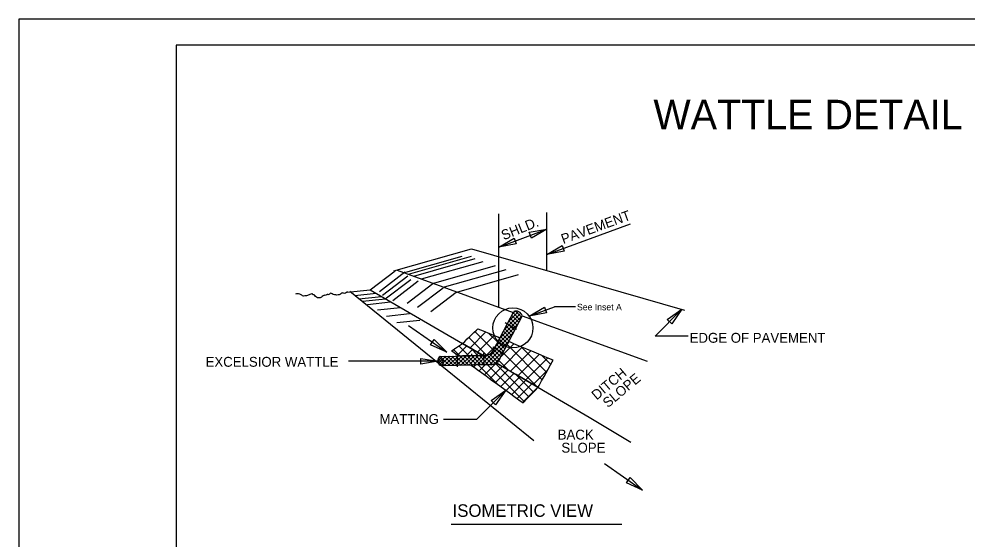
# Model space of a CAD drawing. Extents: x 8096 to 9796, y 9620 to 10720.
# Drawn here: x 8096 to 9099, y 10170 to 10720 of the extents above; entities that cross this region are included whole.
import ezdxf

# ---------------------------------------------------------------- set-up
doc = ezdxf.new("R2010")
doc.units = 0
for name, color, linetype in [('Blank Plan Sheet Both CELL', 7, 'Continuous'), ('Default', 7, 'Continuous'), ('Old_Level_1', 7, 'Continuous'), ('Old_Level_2', 7, 'Continuous'), ('Sheet Plot Border Outside CELL', 7, 'Continuous')]:
    doc.layers.add(name, color=color, linetype=linetype)

msp = doc.modelspace()

# ---------------------------------------------------------------- linework, layer by layer
at = {"layer": 'Blank Plan Sheet Both CELL'}
msp.add_line((8262, 10692.3), (8262, 10692.3), dxfattribs=at)
msp.add_lwpolyline([(9762, 10692.3), (8262, 10692.3), (8262, 9642.3), (9762, 9642.3)], close=True, dxfattribs=at)
at = {"layer": 'Default'}
for p, q in [((8597.6, 10369.4), (8619.1, 10410.3)), ((8597.6, 10369.4), (8619.1, 10410.3)), ((8597.6, 10369.4), (8619.1, 10410.3)), ((8628.1, 10406), (8603.7, 10359.6)), ((8628.1, 10406), (8603.7, 10359.6)), ((8628.1, 10406), (8603.7, 10359.6)), ((8604.2, 10382.1), (8628, 10405.8)), ((8608.9, 10390.9), (8626.6, 10408.6)), ((8613.6, 10399.9), (8624.1, 10410.4)), ((8616.9, 10406.1), (8624.3, 10398.7)), ((8618.3, 10408.8), (8620.1, 10410.6)), ((8618.3, 10408.9), (8625.7, 10401.5)), ((8620.8, 10410.7), (8627.2, 10404.3)), ((8599.5, 10373), (8623.3, 10396.9)), ((8611, 10395), (8618.4, 10387.6)), ((8612.5, 10397.8), (8619.9, 10390.4)), ((8614, 10400.6), (8621.4, 10393.2)), ((8615.4, 10403.4), (8622.8, 10395.9)), ((8572.8, 10372.2), (8589.4, 10388.8)), ((8578, 10389.3), (8597.7, 10369.7)), ((8580.8, 10367.5), (8598.4, 10385.1)), ((8584.7, 10354), (8618.6, 10387.9)), ((8592.5, 10387.6), (8602.1, 10378)), ((8605.2, 10383.9), (8612.6, 10376.5)), ((8606.6, 10386.7), (8614, 10379.3)), ((8608.1, 10389.5), (8615.5, 10382)), ((8609.6, 10392.2), (8617, 10384.8)), ((8559.7, 10364.3), (8569.5, 10374.1)), ((8561.1, 10374.1), (8571.6, 10363.7)), ((8565.1, 10376.8), (8565.5, 10376.4)), ((8571.6, 10383), (8590.4, 10364.3)), ((8589, 10354.1), (8613.9, 10379)), ((8590.3, 10364.2), (8599.9, 10373.8)), ((8600.8, 10375.6), (8608.2, 10368.1)), ((8602.3, 10378.3), (8609.7, 10370.9)), ((8603.7, 10381.1), (8611.1, 10373.7)), ((8605.3, 10362.6), (8619.1, 10376.4)), ((8612, 10375.4), (8649.2, 10338.1)), ((8541.4, 10363), (8589, 10364.1)), ((8541.4, 10363), (8589, 10364.1)), ((8541.4, 10363), (8589, 10364.1)), ((8545.6, 10353.1), (8555.8, 10363.3)), ((8549.9, 10353.2), (8560.1, 10363.4)), ((8553.7, 10363.3), (8563.5, 10353.5)), ((8553.9, 10368.4), (8556.8, 10371.3)), ((8554.2, 10353.3), (8564.5, 10363.5)), ((8555.2, 10370.2), (8561.9, 10363.5)), ((8557.8, 10363.4), (8567.6, 10353.6)), ((8558.6, 10353.4), (8568.8, 10363.6)), ((8562, 10363.5), (8571.7, 10353.7)), ((8562.9, 10353.5), (8573.2, 10363.7)), ((8566.1, 10363.6), (8575.9, 10353.8)), ((8567.3, 10353.6), (8577.5, 10363.8)), ((8568.9, 10363.6), (8575.8, 10370.5)), ((8570.3, 10363.7), (8580, 10353.9)), ((8571.6, 10353.7), (8581.9, 10363.9)), ((8573.2, 10371.9), (8581.2, 10363.9)), ((8574.4, 10363.8), (8584.2, 10354)), ((8576, 10353.8), (8586.2, 10364)), ((8578.5, 10363.9), (8588.3, 10354.1)), ((8579.1, 10363.9), (8582, 10366.8)), ((8580.3, 10353.9), (8590.8, 10364.3)), ((8582.7, 10364), (8592.5, 10354.2)), ((8586.8, 10364.1), (8596.5, 10354.4)), ((8590.8, 10364.3), (8599.6, 10355.5)), ((8593.4, 10354.2), (8609.2, 10370)), ((8593.8, 10365.5), (8602, 10357.3)), ((8596.2, 10367.4), (8603.8, 10359.8)), ((8597.9, 10370), (8605.3, 10362.6)), ((8599.3, 10372.8), (8606.7, 10365.4)), ((8607.5, 10352), (8628.1, 10372.7)), ((8607.6, 10367), (8643.6, 10331)), ((8615.5, 10347.4), (8637.1, 10368.9)), ((8623.6, 10342.7), (8646, 10365.1)), ((8626.9, 10373.1), (8653.8, 10346.3)), ((8648.8, 10364), (8658.3, 10354.5)), ((8538.6, 10357.9), (8542.6, 10361.9)), ((8538.6, 10358.2), (8543.3, 10353.5)), ((8539.1, 10360.5), (8544.2, 10355.5)), ((8539.2, 10355.7), (8543.7, 10360.2)), ((8540.3, 10362.2), (8544.4, 10358.1)), ((8540.5, 10354.2), (8544.4, 10358)), ((8542.1, 10362.4), (8542.8, 10363)), ((8542.3, 10353.2), (8544, 10354.8)), ((8595.1, 10354.2), (8543, 10353)), ((8595.1, 10354.2), (8543, 10353)), ((8595.1, 10354.2), (8543, 10353)), ((8543.4, 10360.8), (8551, 10353.2)), ((8543.9, 10359.9), (8547.1, 10363.1)), ((8544.2, 10355.7), (8546.9, 10353.1)), ((8544.3, 10356.1), (8551.5, 10363.2)), ((8545.4, 10363.1), (8555.2, 10353.3)), ((8549.5, 10363.2), (8559.3, 10353.4)), ((8576.7, 10351.8), (8578.8, 10353.9)), ((8581.6, 10353.9), (8602.2, 10333.3)), ((8582.5, 10347.7), (8588.9, 10354.1)), ((8588.2, 10343.5), (8600.7, 10356)), ((8591.3, 10354.2), (8630.2, 10315.2)), ((8598.2, 10354.9), (8604.5, 10361.1)), ((8599.8, 10355.6), (8635.1, 10320.2)), ((8603.2, 10358.7), (8613.2, 10348.7)), ((8631.6, 10338), (8655, 10361.4)), ((8593.9, 10339.3), (8606.9, 10352.3)), ((8599.7, 10335.2), (8613.2, 10348.7)), ((8605.4, 10331), (8619.5, 10345.1)), ((8621.2, 10344), (8640, 10325.3)), ((8639.6, 10333.3), (8655.2, 10348.8)), ((8611.2, 10326.9), (8625.7, 10341.4)), ((8616.9, 10322.7), (8632, 10337.8)), ((8622.6, 10318.5), (8638.2, 10334.1)), ((8628.4, 10314.4), (8644.5, 10330.5))]:
    msp.add_line(p, q, dxfattribs=at)
for points in [[(8565, 10376.7), (8567.2, 10378.8), (8569.9, 10381.4), (8572.6, 10384), (8576.8, 10388.1), (8579.5, 10390.8), (8581.1, 10392.3), (8586.6, 10390), (8593.6, 10387.1), (8595.2, 10386.5), (8598.3, 10385.2), (8602.2, 10383.5), (8604.5, 10382.5), (8603.5, 10380.6), (8602.6, 10378.9), (8601.4, 10376.7), (8599.8, 10373.7), (8597.9, 10370), (8597.2, 10368.8), (8596.6, 10368), (8595.9, 10367.2), (8595.1, 10366.4), (8594.6, 10366), (8593.7, 10365.5), (8593.1, 10365.1), (8592.4, 10364.8), (8591.8, 10364.6), (8591.3, 10364.4), (8590.7, 10364.3), (8589.9, 10364.2), (8589.2, 10364.1), (8588, 10364.1), (8587.5, 10364.1), (8586.8, 10364.1)], [(8565, 10376.7), (8575.4, 10370.7), (8583.9, 10365.8), (8586.8, 10364.1), (8582.5, 10363.9), (8572.6, 10363.7), (8564.8, 10363.5), (8560.8, 10363.4), (8553.2, 10368.9)], [(8600.6, 10356), (8604.6, 10353.7), (8607.8, 10351.8), (8613.2, 10348.7), (8618.4, 10345.7), (8623.3, 10342.8), (8627.9, 10340.2), (8632, 10337.8), (8637.7, 10334.5), (8641.8, 10332.1), (8644.9, 10330.3), (8645.9, 10332.2), (8648.6, 10337), (8651.2, 10341.8), (8653.4, 10345.6), (8655.5, 10349.4), (8658.1, 10354.2), (8659.7, 10357.1), (8660.8, 10359), (8654.5, 10361.6), (8648.1, 10364.3), (8640.6, 10367.4), (8633, 10370.6), (8624.1, 10374.3), (8619.3, 10376.3), (8616.3, 10377.6), (8613.8, 10378.7), (8612.6, 10376.6), (8612, 10375.4), (8610.7, 10372.9), (8609.2, 10370.1), (8607.4, 10366.6), (8605.5, 10363), (8604.3, 10360.7), (8603.1, 10358.7), (8602.5, 10357.8), (8601.8, 10357), (8601, 10356.4)], [(8600.6, 10356), (8600.1, 10355.7), (8599.5, 10355.4), (8598.9, 10355.1), (8598.1, 10354.8), (8597.5, 10354.6), (8596.5, 10354.4), (8595.9, 10354.3), (8594.5, 10354.3), (8592.9, 10354.2), (8589.7, 10354.1), (8587.4, 10354.1), (8584.5, 10354), (8581.4, 10353.9), (8577.2, 10353.8), (8574.1, 10353.7), (8575.5, 10352.8), (8578.2, 10350.8), (8580.2, 10349.3), (8585, 10345.8), (8589.8, 10342.4), (8595.3, 10338.3), (8601.8, 10333.7), (8608.2, 10329), (8614.6, 10324.3), (8620.7, 10319.9), (8624.5, 10317.2), (8629, 10313.9), (8633.7, 10318.8), (8638, 10323.2), (8641.7, 10327), (8644.9, 10330.3), (8637.2, 10334.8), (8621.7, 10343.7), (8614, 10348.2), (8606.3, 10352.7)]]:
    msp.add_lwpolyline(points, close=True, dxfattribs=at)
msp.add_circle((8618.2, 10393.1), 21.2, dxfattribs=at)
for centre, radius, start, end in [((8621.6, 10404.1), 6.73, 16.3003, 112.3538), ((8621.6, 10404.1), 6.73, 16.3003, 112.3538), ((8621.6, 10404.1), 6.73, 16.3003, 112.3538), ((8588.7, 10374.1), 10, 271.3629, 332.2541), ((8588.7, 10374.1), 10, 271.3629, 332.2541), ((8588.7, 10374.1), 10, 271.3629, 332.2541), ((8543.9, 10358.3), 5.34, 118.1483, 259.9808), ((8537.6, 10357.2), 6.89, 321.9603, 56.1688), ((8537.6, 10357.2), 6.89, 321.9603, 56.1688), ((8537.6, 10357.2), 6.89, 321.9603, 56.1688), ((8537.6, 10357.2), 6.89, 321.9603, 56.1688), ((8537.6, 10357.2), 6.89, 321.9603, 56.1688), ((8594.8, 10364.2), 10, 271.3629, 332.2541), ((8594.8, 10364.2), 10, 271.3629, 332.2541), ((8594.8, 10364.2), 10, 271.3629, 332.2541)]:
    msp.add_arc(centre, radius, start, end, dxfattribs=at)
at = {"layer": 'Old_Level_1'}
for p, q in [((8622, 10391.3), (8610.1, 10398.5)), ((8604.3, 10382.2), (8602.4, 10383.3)), ((8559.6, 10352), (8559.6, 10365.8)), ((8574.7, 10363.5), (8574.7, 10365.8)), ((8587.7, 10352.6), (8587.4, 10366.5)), ((8609, 10365.4), (8597.1, 10372.6))]:
    msp.add_line(p, q, dxfattribs=at)
at = {"layer": 'Old_Level_2'}
for p, q in [((8654, 10501), (8654, 10515.1)), ((8603.3, 10415), (8603.3, 10513.7)), ((8603.3, 10478.5), (8654, 10497.7)), ((8654, 10470.9), (8742.8, 10503.3)), ((8654, 10453.8), (8654, 10501)), ((8492.3, 10453.3), (8574.3, 10476.7)), ((8574.3, 10476.7), (8799.7, 10412)), ((8502.6, 10451.5), (8564.6, 10469.1)), ((8507.7, 10450), (8574.5, 10469)), ((8513.2, 10448), (8578.3, 10466.5)), ((8467.3, 10433.5), (8493.7, 10453.6)), ((8495.8, 10454.1), (8618.6, 10409.4)), ((8521.5, 10444.9), (8586.6, 10463.4)), ((8534.4, 10440.5), (8599.6, 10459)), ((8545.9, 10436.4), (8611, 10455)), ((8477.1, 10431.7), (8504, 10452.3)), ((8480.1, 10427.7), (8507.1, 10448.2)), ((8483.2, 10423.7), (8510.2, 10444.2)), ((8558.9, 10431), (8624.1, 10449.6)), ((8442.8, 10431), (8467.2, 10433.5)), ((8467.3, 10433.5), (8586.8, 10364.1)), ((8491.1, 10422.2), (8518.1, 10442.8)), ((8506.4, 10419.4), (8533.5, 10439.9)), ((8517.4, 10415.1), (8544.3, 10435.6)), ((8445.7, 10431.8), (8539, 10356.3)), ((8451, 10427.4), (8473.6, 10429.8)), ((8455, 10424), (8479, 10426.5)), ((8458.9, 10421.3), (8483.3, 10423.8)), ((8531.3, 10410.4), (8558.3, 10431)), ((8464.2, 10418), (8488.6, 10420.6)), ((8474.8, 10412.2), (8499.2, 10414.7)), ((8635.3, 10405.6), (8662.3, 10415.4)), ((8684.3, 10415.4), (8662.3, 10415.4)), ((8484.5, 10405.7), (8508.9, 10408.3)), ((8628.1, 10406), (8760.4, 10357.9)), ((8495.2, 10398.7), (8519.6, 10401.4)), ((8507.8, 10395.7), (8548.2, 10367.4)), ((8538.6, 10357.9), (8444.2, 10357.9)), ((8600.6, 10356), (8698.9, 10298.8)), ((8543, 10353), (8640.3, 10274.2)), ((8698.9, 10298.8), (8742.9, 10272.4)), ((8715.1, 10249.8), (8755.4, 10221.5)), ((8553, 10185.4), (8733.4, 10185.4))]:
    msp.add_line(p, q, dxfattribs=at)
for points in [[(8654, 10497.7), (8637.8, 10488.1), (8635.5, 10494.2)], [(8603.3, 10478.5), (8619.5, 10488.1), (8621.7, 10482)], [(8654, 10470.9), (8670.2, 10480.3), (8672.5, 10474.2)], [(8635.3, 10405.6), (8651.6, 10415), (8653.9, 10408.9)], [(8797, 10412.8), (8786.2, 10397.4), (8781.6, 10402)], [(8548.2, 10367.4), (8531.1, 10375.3), (8534.9, 10380.7)], [(8538.6, 10357.9), (8520.6, 10354.7), (8520.6, 10360.9)], [(8610.6, 10327.3), (8599.8, 10311.8), (8595.2, 10316.5)], [(8755.4, 10221.5), (8738.4, 10229.4), (8742.1, 10234.8)]]:
    msp.add_lwpolyline(points, close=True, dxfattribs=at)
for points in [[(8803.6, 10384.5), (8768.7, 10384.5), (8797, 10412.8)], [(8610.6, 10327.3), (8579.6, 10296.2), (8544.8, 10296.2)]]:
    msp.add_lwpolyline(points, dxfattribs=at)
msp.add_spline([(8443, 10431.1), (8439.1, 10429.8), (8438.4, 10430.1), (8436.2, 10429.2), (8435.9, 10428.8), (8434.3, 10428.2), (8432, 10427.9), (8426.9, 10429.2), (8425.6, 10429.8), (8422.8, 10428.2), (8421.8, 10428.5), (8420.2, 10427.6), (8418.9, 10427.6), (8415.7, 10425.6), (8410.3, 10425.6), (8406.7, 10428.2), (8406.4, 10428.2), (8406.1, 10429.2), (8405.4, 10429.2), (8401.6, 10427.6), (8399.7, 10427.2), (8398.1, 10426.9), (8395.5, 10427.2), (8394.2, 10428.2), (8392.6, 10428.8), (8390.3, 10429.2), (8388.1, 10428.8)], degree=3, dxfattribs=at)
at = {"layer": 'Sheet Plot Border Outside CELL'}
msp.add_lwpolyline([(8095.5, 9619.8), (9795.5, 9619.8), (9795.5, 10719.8), (8095.5, 10719.8)], close=True, dxfattribs=at)

# ---------------------------------------------------------------- texts
at = {"layer": 'Old_Level_1'}
for s, height, p in [('WATTLE DETAIL', 31.225, (8766.9, 10603.2)), ('See Inset A', 6.859, (8686, 10411.7)), ('EXCELSIOR WATTLE', 10.454, (8293, 10352))]:
    msp.add_text(s, height=height, dxfattribs=at).set_placement(p)
at = {"layer": 'Old_Level_2'}
for s, rotation, p in [('PAVEMENT', 19.9749, (8671.5, 10481.7)), ('SHLD.', 21.9385, (8608.4, 10485.7)), ('DITCH', 39.9471, (8706.8, 10316.3)), (' SLOPE', 39.9471, (8715.7, 10305.6))]:
    msp.add_text(s, height=10.45, rotation=rotation, dxfattribs=at).set_placement(p)
for s, height, p in [('EDGE OF PAVEMENT', 10.454, (8805.2, 10377.4)), ('MATTING', 10.45, (8477, 10291.5)), ('BACK', 10.45, (8665.6, 10275)), (' SLOPE', 10.45, (8665.6, 10261.2)), ('ISOMETRIC VIEW', 13.242, (8554.4, 10193.3))]:
    msp.add_text(s, height=height, dxfattribs=at).set_placement(p)

doc.saveas('drawing.dxf')
